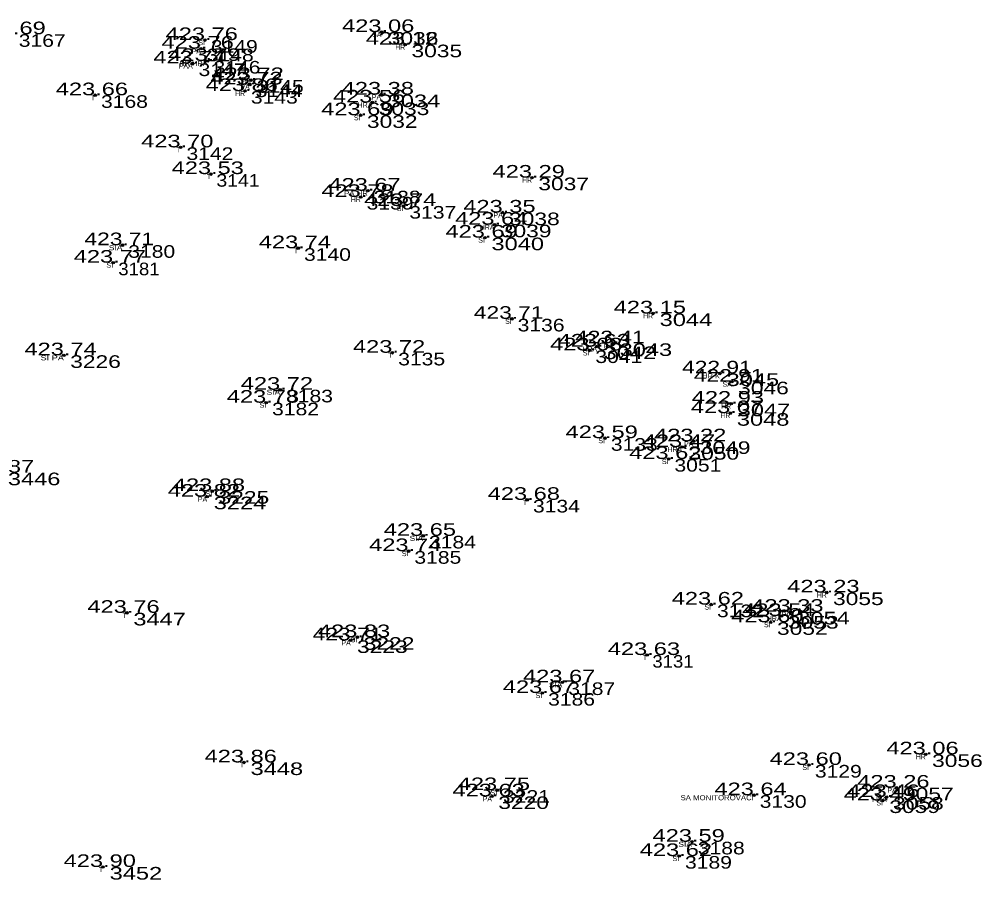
# Model space of a CAD drawing. Extents: x -639390 to -639074, y -1138747 to -1138358.
# Drawn here: x -639201.6 to -639144.4, y -1138568.4 to -1138517.2 of the extents above; entities that cross this region are included whole.
import ezdxf
from ezdxf.enums import TextEntityAlignment as Align

# ---------------------------------------------------------------- set-up
doc = ezdxf.new("R2010")
doc.units = 0
doc.header["$LTSCALE"] = 0.3
doc.header["$PDMODE"] = 32
doc.header["$PDSIZE"] = 0.15
for name, color, linetype in [('11', 7, 'Continuous'), ('12', 7, 'Continuous'), ('13', 7, 'Continuous'), ('57', 7, 'Continuous')]:
    doc.layers.add(name, color=color, linetype=linetype)

msp = doc.modelspace()

# ---------------------------------------------------------------- linework, layer by layer
at = {"layer": '11'}
for p in [(-639180.04, -1138517.92), (-639190.53, -1138518.4), (-639178.63, -1138518.67), (-639190.77, -1138518.91), (-639191.26, -1138519.79), (-639190.37, -1138519.64), (-639187.87, -1138521.04), (-639187.8, -1138520.78), (-639197.06, -1138521.68), (-639188.15, -1138521.43), (-639180.06, -1138521.64), (-639180.58, -1138522.11), (-639181.28, -1138522.87), (-639191.98, -1138524.78), (-639190.17, -1138526.37), (-639171.09, -1138526.58), (-639180.85, -1138527.36), (-639181.27, -1138527.73), (-639178.73, -1138528.27), (-639172.83, -1138528.66), (-639173.32, -1138529.38), (-639173.89, -1138530.15), (-639195.44, -1138530.6), (-639184.99, -1138530.78), (-639195.99, -1138531.64), (-639163.89, -1138534.66), (-639172.29, -1138534.98), (-639166.27, -1138536.44), (-639198.92, -1138537.15), (-639179.39, -1138537), (-639167.67, -1138536.86), (-639167.22, -1138536.63), (-639159.91, -1138538.23), (-639159.21, -1138538.72), (-639186.06, -1138539.2), (-639186.89, -1138539.97), (-639159.25, -1138540.03), (-639159.3, -1138540.59), (-639166.75, -1138542.08), (-639161.49, -1138542.27), (-639162.16, -1138542.61), (-639162.97, -1138543.32), (-639190.4, -1138545.56), (-639190.1, -1138545.23), (-639171.38, -1138545.75), (-639177.56, -1138547.89), (-639178.43, -1138548.8), (-639153.57, -1138551.26), (-639160.44, -1138551.98), (-639195.18, -1138552.47), (-639155.71, -1138552.41), (-639156.9, -1138553.03), (-639156.25, -1138552.66), (-639181.87, -1138554.11), (-639181.47, -1138553.92), (-639164.24, -1138554.98), (-639169.28, -1138556.61), (-639170.48, -1138557.24), (-639147.68, -1138560.89), (-639188.21, -1138561.37), (-639154.62, -1138561.52), (-639149.41, -1138562.87), (-639173.47, -1138563.39), (-639173.16, -1138563.02), (-639157.9, -1138563.32), (-639150, -1138563.43), (-639150.22, -1138563.63), (-639161.58, -1138566.09), (-639162.34, -1138566.94), (-639196.59, -1138567.59)]:
    msp.add_point(p, dxfattribs=at)

# ---------------------------------------------------------------- texts
at = {"layer": '12'}
for s, width, p in [('423.69 ', 1.4, (-639201.95, -1138518.05)), ('423.76 ', 1.4, (-639190.529, -1138518.4)), ('423.06 ', 1.4, (-639180.039, -1138517.92)), ('423.76 ', 1.4, (-639190.769, -1138518.91)), ('423.12 ', 1.4, (-639178.63, -1138518.67)), ('423.74 ', 1.4, (-639191.26, -1138519.79)), ('423.79 ', 1.4, (-639190.37, -1138519.64)), ('423.73 ', 1.4, (-639187.87, -1138521.04)), ('423.72 ', 1.4, (-639187.8, -1138520.78)), ('423.66 ', 1.4, (-639197.059, -1138521.68)), ('423.86 ', 1.4, (-639188.149, -1138521.43)), ('423.38 ', 1.4, (-639180.06, -1138521.64)), ('423.56 ', 1.4, (-639180.579, -1138522.11)), ('423.69 ', 1.4, (-639181.28, -1138522.87)), ('423.70 ', 1.4, (-639191.98, -1138524.78)), ('423.53 ', 1.4, (-639190.17, -1138526.37)), ('423.29 ', 1.4, (-639171.09, -1138526.58)), ('423.67 ', 1.4, (-639180.85, -1138527.36)), ('423.78 ', 1.4, (-639181.27, -1138527.73)), ('423.74 ', 1.4, (-639178.73, -1138528.27)), ('423.35 ', 1.4, (-639172.83, -1138528.66)), ('423.64 ', 1.4, (-639173.32, -1138529.38)), ('423.69 ', 1.4, (-639173.89, -1138530.15)), ('423.71 ', 1.35, (-639195.439, -1138530.6)), ('423.74 ', 1.4, (-639184.99, -1138530.78)), ('423.77 ', 1.4, (-639195.99, -1138531.64)), ('423.71 ', 1.35, (-639172.289, -1138534.98)), ('423.15 ', 1.4, (-639163.89, -1138534.66)), ('423.63 ', 1.4, (-639167.22, -1138536.63)), ('423.41 ', 1.35, (-639166.269, -1138536.44)), ('423.74 ', 1.4, (-639198.92, -1138537.15)), ('423.72 ', 1.4, (-639179.39, -1138537)), ('423.68 ', 1.4, (-639167.67, -1138536.86)), ('422.91 ', 1.35, (-639159.909, -1138538.23)), ('422.91 ', 1.35, (-639159.209, -1138538.72)), ('423.72 ', 1.4, (-639186.06, -1138539.2)), ('423.78 ', 1.4, (-639186.89, -1138539.97)), ('422.93 ', 1.4, (-639159.25, -1138540.03)), ('423.07 ', 1.4, (-639159.3, -1138540.59)), ('423.59 ', 1.4, (-639166.75, -1138542.08)), ('423.22 ', 1.4, (-639161.49, -1138542.27)), ('423.47 ', 1.4, (-639162.16, -1138542.61)), ('423.62 ', 1.4, (-639162.97, -1138543.32)), ('423.87 ', 1.4, (-639202.64, -1138544.13)), ('423.88 ', 1.4, (-639190.1, -1138545.23)), ('423.82 ', 1.4, (-639190.4, -1138545.56)), ('423.68 ', 1.4, (-639171.38, -1138545.75)), ('423.65 ', 1.4, (-639177.56, -1138547.89)), ('423.74 ', 1.4, (-639178.43, -1138548.8)), ('423.23 ', 1.4, (-639153.57, -1138551.26)), ('423.62 ', 1.4, (-639160.44, -1138551.98)), ('423.76 ', 1.4, (-639195.179, -1138552.47)), ('423.54 ', 1.4, (-639156.25, -1138552.66)), ('423.33 ', 1.4, (-639155.71, -1138552.41)), ('423.60 ', 1.4, (-639156.9, -1138553.03)), ('423.71 ', 1.35, (-639181.869, -1138554.11)), ('423.83 ', 1.4, (-639181.47, -1138553.92)), ('423.63 ', 1.4, (-639164.24, -1138554.98)), ('423.67 ', 1.4, (-639169.28, -1138556.61)), ('423.67 ', 1.4, (-639170.48, -1138557.24)), ('423.06 ', 1.4, (-639147.679, -1138560.89)), ('423.86 ', 1.4, (-639188.209, -1138561.37)), ('423.60 ', 1.4, (-639154.62, -1138561.52)), ('423.75 ', 1.4, (-639173.16, -1138563.02)), ('423.26 ', 1.4, (-639149.409, -1138562.87)), ('423.63 ', 1.4, (-639173.47, -1138563.39)), ('423.64 ', 1.4, (-639157.9, -1138563.32)), ('423.46 ', 1.4, (-639149.999, -1138563.43)), ('423.49 ', 1.4, (-639150.22, -1138563.63)), ('423.59 ', 1.4, (-639161.58, -1138566.09)), ('423.62 ', 1.4, (-639162.34, -1138566.94)), ('423.90 ', 1.4, (-639196.59, -1138567.59))]:
    msp.add_text(s, height=0.75, dxfattribs=dict(at, width=width)).set_placement(p, align=Align.CENTER)
at = {"layer": '13'}
for s, width, p in [(' 3167', 1.25, (-639201.95, -1138518.8)), (' 3036', 1.35, (-639180.04, -1138518.67)), (' 3149', 1.25, (-639190.53, -1138519.15)), (' 3035', 1.35, (-639178.63, -1138519.42)), (' 3148', 1.25, (-639190.77, -1138519.66)), (' 3147', 1.25, (-639191.26, -1138520.54)), (' 3146', 1.25, (-639190.37, -1138520.39)), (' 3144', 1.25, (-639187.87, -1138521.79)), (' 3145', 1.25, (-639187.8, -1138521.53)), (' 3143', 1.25, (-639188.15, -1138522.18)), (' 3034', 1.4, (-639180.06, -1138522.39)), (' 3168', 1.25, (-639197.06, -1138522.43)), (' 3033', 1.35, (-639180.58, -1138522.86)), (' 3032', 1.35, (-639181.28, -1138523.62)), (' 3142', 1.25, (-639191.98, -1138525.53)), (' 3141', 1.15, (-639190.17, -1138527.12)), (' 3037', 1.35, (-639171.09, -1138527.33)), (' 3138', 1.25, (-639180.85, -1138528.11)), (' 3139', 1.25, (-639181.27, -1138528.48)), (' 3137', 1.25, (-639178.73, -1138529.02)), (' 3038', 1.35, (-639172.83, -1138529.41)), (' 3039', 1.35, (-639173.32, -1138530.13)), (' 3040', 1.4, (-639173.89, -1138530.9)), (' 3180', 1.25, (-639195.44, -1138531.35)), (' 3140', 1.25, (-639184.99, -1138531.53)), (' 3181', 1.1, (-639195.99, -1138532.39)), (' 3044', 1.4, (-639163.89, -1138535.41)), (' 3136', 1.25, (-639172.29, -1138535.73)), (' 3043', 1.4, (-639166.27, -1138537.19)), (' 3135', 1.25, (-639179.39, -1138537.75)), (' 3041', 1.25, (-639167.67, -1138537.61)), (' 3042', 1.4, (-639167.22, -1138537.38)), (' 3226', 1.35, (-639198.92, -1138537.9)), (' 3045', 1.4, (-639159.91, -1138538.98)), (' 3046', 1.35, (-639159.21, -1138539.47)), (' 3183', 1.25, (-639186.06, -1138539.95)), (' 3182', 1.25, (-639186.89, -1138540.72)), (' 3047', 1.4, (-639159.25, -1138540.78)), (' 3048', 1.4, (-639159.3, -1138541.34)), (' 3133', 1.25, (-639166.75, -1138542.83)), (' 3049', 1.35, (-639161.49, -1138543.02)), (' 3050', 1.35, (-639162.16, -1138543.36)), (' 3051', 1.25, (-639162.97, -1138544.07)), (' 3446', 1.4, (-639202.64, -1138544.88)), (' 3224', 1.4, (-639190.4, -1138546.31)), (' 3225', 1.35, (-639190.1, -1138545.98)), (' 3134', 1.25, (-639171.38, -1138546.5)), (' 3184', 1.25, (-639177.56, -1138548.64)), (' 3185', 1.25, (-639178.43, -1138549.55)), (' 3055', 1.35, (-639153.57, -1138552.01)), (' 3132', 1.25, (-639160.44, -1138552.73)), (' 3447', 1.4, (-639195.18, -1138553.22)), (' 3054', 1.4, (-639155.71, -1138553.16)), (' 3052', 1.35, (-639156.9, -1138553.78)), (' 3053', 1.35, (-639156.25, -1138553.41)), (' 3223', 1.35, (-639181.87, -1138554.86)), (' 3222', 1.35, (-639181.47, -1138554.67)), (' 3131', 1.1, (-639164.24, -1138555.73)), (' 3187', 1.25, (-639169.28, -1138557.36)), (' 3186', 1.25, (-639170.48, -1138557.99)), (' 3056', 1.35, (-639147.68, -1138561.64)), (' 3448', 1.4, (-639188.21, -1138562.12)), (' 3129', 1.25, (-639154.62, -1138562.27)), (' 3057', 1.35, (-639149.41, -1138563.62)), (' 3220', 1.35, (-639173.47, -1138564.14)), (' 3221', 1.25, (-639173.16, -1138563.77)), (' 3130', 1.25, (-639157.9, -1138564.07)), (' 3058', 1.35, (-639150, -1138564.18)), (' 3059', 1.35, (-639150.22, -1138564.38)), (' 3188', 1.25, (-639161.58, -1138566.84)), (' 3189', 1.25, (-639162.34, -1138567.69)), (' 3452', 1.4, (-639196.59, -1138568.34))]:
    msp.add_text(s, height=0.75, dxfattribs=dict(at, width=width)).set_placement(p)
at = {"layer": '57'}
for s, width, p in [('SA', 0.95, (-639180.04, -1138518.22)), ('SI', 1.05, (-639190.53, -1138518.7)), ('HR', 0.85, (-639178.629, -1138518.97)), ('PA', 0.95, (-639190.77, -1138519.21)), ('HR HRA', 1.1, (-639190.37, -1138519.94)), ('PA', 0.95, (-639187.87, -1138521.34)), ('SI', 1.05, (-639187.8, -1138521.08)), ('HR', 0.85, (-639188.149, -1138521.73)), ('PA', 0.95, (-639180.06, -1138521.94)), ('T', 0.85, (-639197.06, -1138521.98)), ('HRA', 0.95, (-639180.58, -1138522.41)), ('SI', 1.05, (-639181.28, -1138523.17)), ('T', 0.85, (-639191.98, -1138525.08)), ('T', 0.85, (-639190.17, -1138526.67)), ('HR', 0.85, (-639171.089, -1138526.88)), ('PA HR', 1.15, (-639180.849, -1138527.66)), ('HR', 0.85, (-639181.269, -1138528.03)), ('SI', 1.05, (-639178.73, -1138528.57)), ('PA', 0.95, (-639172.83, -1138528.96)), ('HRA', 0.95, (-639173.32, -1138529.68)), ('SI', 1.05, (-639173.89, -1138530.45)), ('SIA', 1.25, (-639195.44, -1138530.9)), ('T', 0.85, (-639184.99, -1138531.08)), ('SI', 1.05, (-639195.99, -1138531.94)), ('HR', 0.85, (-639163.889, -1138534.96)), ('SI', 1.05, (-639172.29, -1138535.28)), ('PA', 0.95, (-639166.27, -1138536.74)), ('T', 0.85, (-639179.39, -1138537.3)), ('SI', 1.05, (-639167.67, -1138537.16)), ('HRA', 0.95, (-639167.22, -1138536.93)), ('SI PA', 1.35, (-639198.92, -1138537.45)), ('HR K', 1.1, (-639159.909, -1138538.53)), ('SA', 0.95, (-639159.21, -1138539.02)), ('SIA', 1.25, (-639186.06, -1138539.5)), ('SI', 1.05, (-639186.89, -1138540.27)), ('HR', 0.85, (-639159.249, -1138540.33)), ('HR', 0.85, (-639159.299, -1138540.89)), ('SI', 1.05, (-639166.75, -1138542.38)), ('HRA', 0.95, (-639162.16, -1138542.91)), ('PA', 0.95, (-639161.49, -1138542.57)), ('SI', 1.05, (-639162.97, -1138543.62)), ('PA', 0.95, (-639190.4, -1138545.86)), ('SI', 1.05, (-639190.1, -1138545.53)), ('T', 0.85, (-639171.38, -1138546.05)), ('SIA', 1.25, (-639177.56, -1138548.19)), ('SI', 1.05, (-639178.43, -1138549.1)), ('HR', 0.85, (-639153.569, -1138551.56)), ('SI', 1.05, (-639160.44, -1138552.28)), ('T', 0.85, (-639195.18, -1138552.77)), ('PA', 0.95, (-639155.71, -1138552.71)), ('SI', 1.05, (-639156.9, -1138553.33)), ('HRA', 0.95, (-639156.25, -1138552.96)), ('PA', 0.95, (-639181.87, -1138554.41)), ('SI', 1.05, (-639181.47, -1138554.22)), ('T', 0.85, (-639164.24, -1138555.28)), ('SIA', 1.25, (-639169.28, -1138556.91)), ('SI', 1.05, (-639170.48, -1138557.54)), ('HR', 0.85, (-639147.679, -1138561.19)), ('T', 0.85, (-639188.21, -1138561.67)), ('SI', 1.05, (-639154.62, -1138561.82)), ('PA', 0.95, (-639173.47, -1138563.69)), ('SI', 1.05, (-639173.16, -1138563.32)), ('SA MONITOROVACI', 1.15, (-639157.9, -1138563.62)), ('HRA', 0.95, (-639150, -1138563.73)), ('PA', 0.95, (-639149.41, -1138563.17)), ('SI', 1.05, (-639150.22, -1138563.93)), ('SIA', 1.25, (-639161.58, -1138566.39)), ('SI', 1.05, (-639162.34, -1138567.24)), ('T', 0.85, (-639196.59, -1138567.89))]:
    msp.add_text(s, height=0.3, dxfattribs=dict(at, width=width)).set_placement(p, align=Align.RIGHT)
msp.add_text('PAA', height=0.3, dxfattribs=at).set_placement((-639191.26, -1138520.09), align=Align.RIGHT)

doc.saveas('drawing.dxf')
